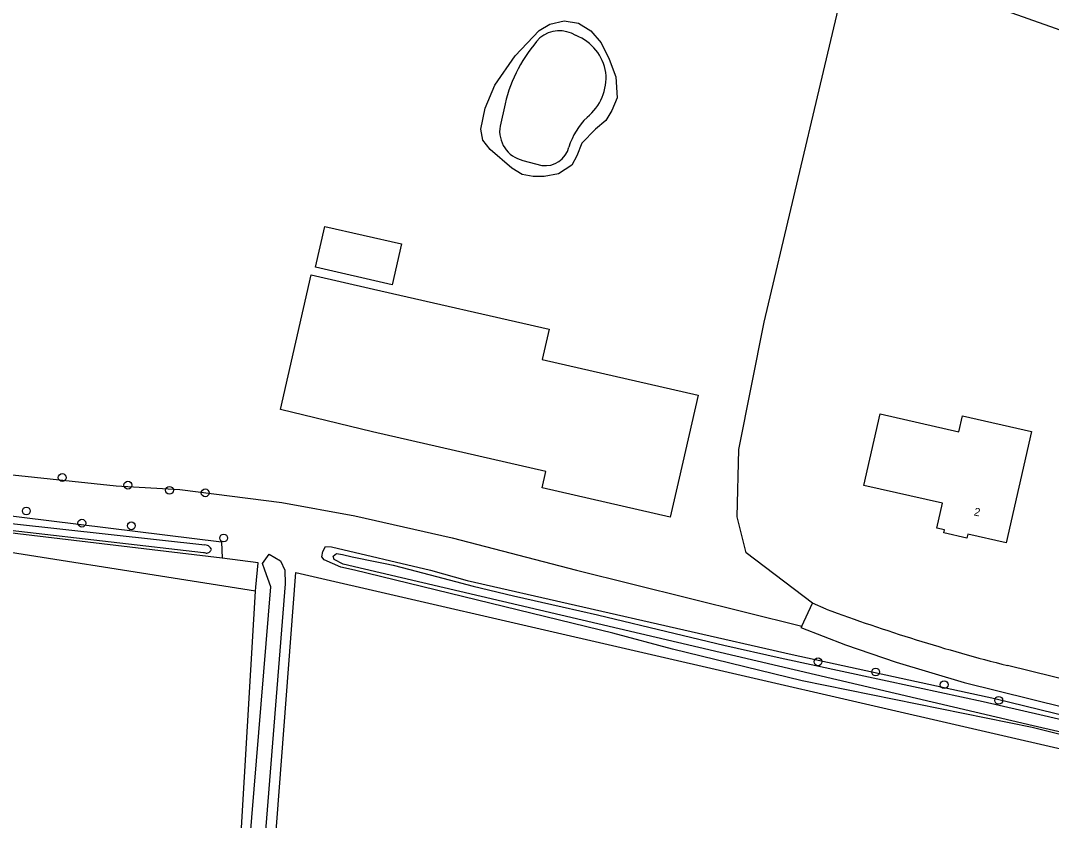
# Model space of a CAD drawing. Extents: x 162722 to 165099, y 384721 to 386283.
# Drawn here: x 164590.2 to 164719, y 385468.8 to 385568.7 of the extents above; entities that cross this region are included whole.
import ezdxf

# ---------------------------------------------------------------- set-up
doc = ezdxf.new("R2010")
doc.units = 0
for name, color, linetype in [('IMGEO_Boom', 7, 'Continuous'), ('IMGEO_Erf', 7, 'Continuous'), ('IMGEO_Grasland_agrarisch', 7, 'Continuous'), ('IMGEO_Grasland_overig', 7, 'Continuous'), ('IMGEO_Groenvoorziening', 7, 'Continuous'), ('IMGEO_Hek', 7, 'Continuous'), ('IMGEO_Meer_plas_ven_vijver', 7, 'Continuous'), ('IMGEO_Pand', 7, 'Continuous'), ('IMGEO_Pand_nummerreeks', 7, 'Continuous'), ('IMGEO_Rijbaan_lokaal_open', 7, 'Continuous'), ('IMGEO_Waterloop', 7, 'Continuous')]:
    doc.layers.add(name, color=color, linetype=linetype)

msp = doc.modelspace()

# ---------------------------------------------------------------- linework, layer by layer
at = {"layer": 'IMGEO_Boom'}
for centre in [(164595.41, 385511.59), (164603.62, 385510.64), (164608.81, 385509.99), (164613.28, 385509.67), (164590.93, 385507.41), (164597.87, 385505.89), (164604.05, 385505.56), (164615.59, 385504.03), (164689.85, 385488.57), (164697.05, 385487.29), (164705.61, 385485.71), (164712.43, 385483.75)]:
    msp.add_circle(centre, 0.489, dxfattribs=at)
at = {"layer": 'IMGEO_Erf'}
msp.add_lwpolyline([(164694.22, 385578.02), (164696.35, 385577.13), (164706.54, 385572.33), (164722.91, 385566.51), (164731.38, 385562.94), (164732.93, 385562.52), (164736.5, 385561.21), (164737.84, 385560.72), (164741.18, 385559.22)], dxfattribs=at)
at = {"layer": 'IMGEO_Grasland_agrarisch'}
for points in [[(164689.15, 385495.9), (164680.89, 385502.19), (164679.75, 385506.66), (164679.95, 385515.09), (164683.11, 385530.99), (164694.22, 385578.02)], [(164655.62, 385549.21), (164654.27, 385549.2), (164652.89, 385549.46), (164651.58, 385550.25), (164648.89, 385552.56), (164647.97, 385553.75), (164647.73, 385555.1), (164648.26, 385557.72), (164649.45, 385560.6), (164651.99, 385564.28), (164655.01, 385567.45), (164656.36, 385568.24), (164658.13, 385568.65), (164659.92, 385568.35), (164661.46, 385567.4), (164662.74, 385565.91), (164663.75, 385563.84), (164664.58, 385561.65), (164664.75, 385559.01), (164664.07, 385557.46), (164663.32, 385556.19), (164662.06, 385555.13), (164660.34, 385553.37), (164659.71, 385551.77), (164659.08, 385550.61), (164657.41, 385549.55), (164655.62, 385549.21)], [(164528.33, 385530.08), (164530.83, 385535.25), (164539.05, 385530.5), (164540.88, 385529.27), (164544.16, 385527.07), (164547.36, 385525.2), (164550.38, 385523.48), (164565.7, 385516.85), (164574.56, 385514.11), (164583.67, 385512.51), (164602.17, 385510.55), (164610.12, 385510.08), (164622.86, 385508.46), (164631.96, 385506.81), (164644.12, 385504.06), (164659.68, 385500), (164687.81, 385493.04)], [(164614.9, 385349.51), (164616.06, 385349.46), (164616.6, 385363.28), (164618.45, 385418.71), (164624.59, 385499.73), (164751.42, 385470.5), (164765.25, 385467.3), (164760.61, 385455.24), (164753.39, 385437.01), (164741.58, 385408.04), (164709.86, 385327.3), (164709.38, 385326.07), (164702.89, 385326.69), (164679.55, 385328.8), (164662.73, 385330.29), (164654.38, 385330.82), (164636.82, 385332.4), (164626.27, 385334.44), (164619.62, 385337.27), (164617.3, 385342.33), (164617.04, 385344.33), (164616.13, 385344.62), (164614.75, 385344.92)], [(164612.79, 385349.95), (164612.18, 385350.13), (164612.92, 385384.85), (164619.57, 385497.4)]]:
    msp.add_lwpolyline(points, dxfattribs=at)
at = {"layer": 'IMGEO_Grasland_overig'}
for points in [[(164615.4, 385501.52), (164578.29, 385505.91), (164577.12, 385505.75), (164576.57, 385504.83), (164575.56, 385500), (164566.9, 385448.97), (164566.24, 385444.69), (164562.06, 385417.82), (164559.78, 385403.18), (164555.57, 385380.06)], [(164619.57, 385497.4), (164577.84, 385503.96), (164575.43, 385487.2), (164569.86, 385454.04), (164563.47, 385420.91), (164556.55, 385379.99), (164555.57, 385380.06)], [(164619.57, 385497.4), (164619.6, 385497.88), (164619.89, 385500.92), (164615.4, 385501.52)]]:
    msp.add_lwpolyline(points, dxfattribs=at)
at = {"layer": 'IMGEO_Groenvoorziening'}
for points in [[(164560.73, 385513.13), (164565.85, 385511.52), (164576.51, 385508.79), (164583.23, 385507.52), (164615.31, 385503.55), (164615.4, 385501.52)], [(164671.66, 385490.15), (164664.21, 385492.14), (164631.92, 385500), (164630.21, 385500.41), (164628.14, 385501.29), (164627.86, 385501.69), (164627.98, 385502.33), (164628.33, 385502.97), (164629.04, 385502.95), (164641.44, 385500), (164646.03, 385498.73), (164686.61, 385489.48), (164711.94, 385484), (164728.63, 385479.9), (164736, 385478.33), (164758.73, 385472.55)], [(164759.75, 385470.42), (164753.87, 385471.54), (164727.07, 385477.75), (164716.62, 385480.37), (164687.88, 385486.21), (164671.66, 385490.15)]]:
    msp.add_lwpolyline(points, dxfattribs=at)
at = {"layer": 'IMGEO_Hek'}
msp.add_lwpolyline([(164659.68, 385500), (164687.81, 385493.04)], dxfattribs=at)
at = {"layer": 'IMGEO_Meer_plas_ven_vijver'}
for points in [[(164650.74, 385558.27), (164650.13, 385555.5)], [(164652.98, 385551.2), (164655.33, 385550.58)]]:
    msp.add_lwpolyline(points, dxfattribs=at)
for centre, radius, start, end in [((164657.55, 385563.43), 3.96, 58.7273, 128.6287), ((164657.39, 385561.21), 6.03, 9.337, 68.3889), ((164669.2, 385553.84), 18.98, 138.0601, 166.5081), ((164657.03, 385561.55), 6.34, 308.5844, 5.8206), ((164667.68, 385549.93), 9.44, 135.1801, 161.8121), ((164653.84, 385554.87), 3.77, 170.3235, 256.7304), ((164655.78, 385553.57), 3.02, 261.4597, 346.7984)]:
    msp.add_arc(centre, radius, start, end, dxfattribs=at)
at = {"layer": 'IMGEO_Pand'}
for points in [[(164637.8, 385540.78), (164636.63, 385535.67), (164627.08, 385537.85), (164628.24, 385542.96), (164637.8, 385540.78)], [(164626.51, 385536.91), (164634.29, 385535.14), (164656.25, 385530.13), (164655.38, 385526.32), (164674.86, 385521.88), (164672.49, 385511.53), (164671.38, 385506.65), (164655.37, 385510.3), (164655.84, 385512.36), (164634.18, 385517.3), (164622.67, 385520.09), (164626.51, 385536.91)], [(164713.36, 385503.42), (164708.55, 385504.52), (164708.44, 385504.01), (164705.56, 385504.67), (164705.65, 385505.04), (164704.68, 385505.27), (164705.39, 385508.37), (164695.57, 385510.61), (164697.61, 385519.54), (164707.45, 385517.29), (164707.91, 385519.28), (164716.53, 385517.32), (164713.36, 385503.42)]]:
    msp.add_lwpolyline(points, dxfattribs=at)
at = {"layer": 'IMGEO_Rijbaan_lokaal_open'}
for points in [[(164687.81, 385493.04), (164689.15, 385495.9)], [(164690.85, 385495.16), (164689.15, 385495.9)], [(164687.81, 385493.04), (164687.72, 385492.85), (164693.27, 385490.68), (164699.63, 385488.52), (164708.11, 385485.98), (164758.24, 385473.57), (164766.79, 385471.42), (164769.58, 385470.19)], [(164767.66, 385474.96), (164767.62, 385474.77), (164713.52, 385488.1)]]:
    msp.add_lwpolyline(points, dxfattribs=at)
msp.add_arc((164768.38, 385704.09), 222.85, 249.6431, 255.7505, dxfattribs=at)
at = {"layer": 'IMGEO_Waterloop'}
for points in [[(164561.17, 385510.97), (164560.86, 385511.07), (164560.54, 385511.24), (164560.29, 385511.48), (164560.21, 385511.7), (164560.21, 385511.8), (164560.32, 385512.13), (164560.39, 385512.21), (164560.56, 385512.29), (164560.89, 385512.26), (164561.27, 385512.13), (164576.26, 385507.16), (164583.36, 385506.49), (164613.24, 385503.19)], [(164613.37, 385502.15), (164613.21, 385502.17), (164613.06, 385502.19), (164578.4, 385506.16), (164577.58, 385506.17), (164577.09, 385505.95), (164576.35, 385505.44), (164576.02, 385504.98), (164574.66, 385499.6), (164570.57, 385474.92), (164569.16, 385467.14), (164561.92, 385419.48), (164557.83, 385396.54), (164555.19, 385380.99), (164555.11, 385380.77)], [(164614.01, 385502.68), (164614.02, 385502.58)], [(164612.79, 385349.95), (164614.09, 385390.64), (164615.01, 385406.88), (164615.69, 385422.36), (164616.6, 385433.6), (164617.01, 385443.83), (164621.48, 385497.93), (164620.74, 385500), (164620.43, 385500.85), (164621.26, 385502.02), (164622.67, 385501.2), (164623.23, 385500), (164623.26, 385498.29), (164620.63, 385465.38), (164619.74, 385452.49), (164618.84, 385435.01), (164617.83, 385419.2), (164615.32, 385366.81), (164614.9, 385349.51)], [(164629.26, 385501.78), (164629.7, 385502.1), (164630.43, 385501.97), (164631.65, 385501.67), (164632.67, 385501.47), (164633.7, 385501.28), (164635.75, 385500.87), (164636.76, 385500.64), (164638.86, 385500.12), (164643.77, 385498.79), (164646.78, 385498), (164651.82, 385496.79), (164657.89, 385495.43), (164662.3, 385494.44), (164672.01, 385492.1), (164678.06, 385490.65), (164685.14, 385489.07), (164697.31, 385486.46), (164702.37, 385485.37), (164710.47, 385483.59), (164717.55, 385481.99), (164725.63, 385480.11)], [(164757.55, 385471.21), (164716.73, 385480.56), (164630.51, 385500.75), (164629.39, 385501.33), (164629.26, 385501.78)]]:
    msp.add_lwpolyline(points, dxfattribs=at)
for centre, radius, start, end in [((164613.15, 385502.1), 1.09, 51.1637, 84.7598), ((164613.41, 385502.85), 0.703, 266.827, 306.387), ((164613.45, 385502.49), 0.593, 18.576, 50.3685), ((164613.58, 385502.67), 0.456, 303.2896, 348.0499)]:
    msp.add_arc(centre, radius, start, end, dxfattribs=at)

# ---------------------------------------------------------------- texts
at = {"layer": 'IMGEO_Pand_nummerreeks'}
msp.add_text('2', height=1, rotation=348.0292, dxfattribs=at).set_placement((164709.27, 385506.87))

doc.saveas('drawing.dxf')
